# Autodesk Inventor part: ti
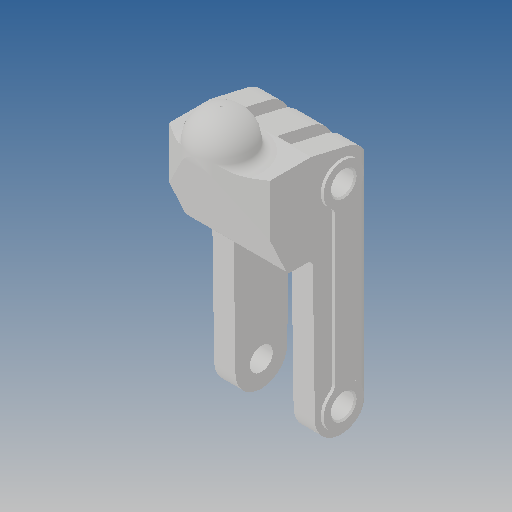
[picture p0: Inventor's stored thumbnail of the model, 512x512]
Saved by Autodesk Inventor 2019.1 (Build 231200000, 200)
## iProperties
Created: 2012-10
Part Number: ti
Material: Ogólny
Document SubType Name: Modeling
Designer: CADENGINEERING4
Density: 1 g/cm^3
Appearance: Domyślna
Author: CADENGINEERING4
Revision Number: ÈÎºÎ
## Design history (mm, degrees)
feature "µ¹½Ç1"
node "Bryła1"
